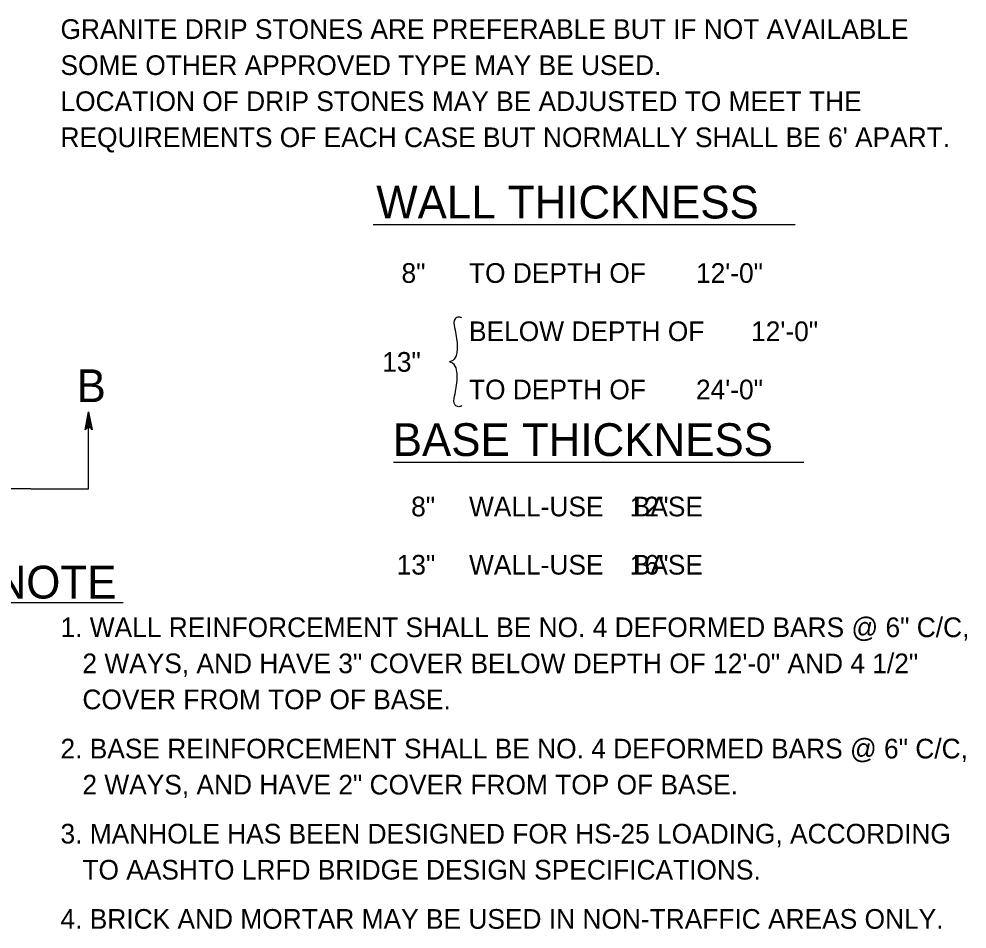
# Model space of a CAD drawing. Extents: x 0.2 to 7.1, y 1.2 to 11.2.
# Drawn here: x 3.289 to 6.18, y 8.474 to 11.25 of the extents above; entities that cross this region are included whole.
import ezdxf

# ---------------------------------------------------------------- set-up
doc = ezdxf.new("R2010")
doc.units = 0
for name, color, linetype in [('DETL-DIMS', 7, 'Continuous'), ('DETL-NOTE', 7, 'Continuous'), ('DETL-TITL', 7, 'Continuous')]:
    doc.layers.add(name, color=color, linetype=linetype)

msp = doc.modelspace()

# ---------------------------------------------------------------- linework, layer by layer
at = {"layer": 'DETL-DIMS'}
for p, q in [((3.5011, 9.8165), (3.5011, 10.0518)), ((3.3247, 9.8165), (2.4784, 9.8165)), ((3.3247, 9.8165), (3.5011, 9.8165))]:
    msp.add_line(p, q, dxfattribs=at)
msp.add_lwpolyline([(3.5011, 10.0518), (3.5114, 9.997), (3.5085, 10.0012), (3.5048, 10.0034), (3.5011, 10.004), (3.4975, 10.0034), (3.4938, 10.0012), (3.4909, 9.997), (3.5011, 10.0518), (3.4938, 10.0012), (3.4975, 10.0034), (3.5011, 10.0518), (3.5011, 10.004), (3.5048, 10.0034), (3.5011, 10.0518), (3.5085, 10.0012)], dxfattribs=at)
at = {"layer": 'DETL-NOTE'}
msp.add_line((3.2189, 9.4698), (3.6066, 9.4698), dxfattribs=at)
for points in [[(4.6393, 10.3383), (4.6303, 10.3406), (4.6187, 10.3357), (4.6171, 10.3087), (4.6219, 10.2817), (4.6251, 10.2533), (4.6115, 10.2087), (4.6017, 10.2038)], [(4.6393, 10.0697), (4.6303, 10.0674), (4.6187, 10.0723), (4.6171, 10.0993), (4.6219, 10.1263), (4.6251, 10.1547), (4.6115, 10.1993), (4.6017, 10.2042)]]:
    msp.add_spline(points, degree=3, dxfattribs=at)
at = {"layer": 'DETL-TITL'}
for p, q in [((4.3687, 10.6228), (5.6556, 10.6228)), ((4.431, 9.8983), (5.682, 9.8983))]:
    msp.add_line(p, q, dxfattribs=at)

# ---------------------------------------------------------------- texts
at = {"layer": 'DETL-NOTE'}
for s, height, p in [('GRANITE DRIP STONES ARE PREFERABLE BUT IF NOT AVAILABLE', 0.06, (3.4153, 11.189)), ('SOME OTHER APPROVED TYPE MAY BE USED.', 0.06, (3.4153, 11.079)), ('LOCATION OF DRIP STONES MAY BE ADJUSTED TO MEET THE', 0.06, (3.4153, 10.969)), ("REQUIREMENTS OF EACH CASE BUT NORMALLY SHALL BE 6' APART.", 0.06, (3.4153, 10.859)), ('8"', 0.06, (4.4552, 10.4451)), ('TO DEPTH OF ', 0.06, (4.661, 10.4451)), ('12\'-0"', 0.06, (5.3531, 10.4451)), ('BELOW DEPTH OF', 0.06, (4.661, 10.2674)), ('12\'-0"', 0.06, (5.5212, 10.2674)), ('13"', 0.06, (4.3963, 10.174)), ('B', 0.1, (3.4644, 10.0812)), ('TO DEPTH OF', 0.06, (4.661, 10.0898)), ('24\'-0"', 0.06, (5.3531, 10.0898)), ('8"', 0.06, (4.4846, 9.7329)), ('WALL-USE    BASE', 0.06, (4.661, 9.7329)), ('12"', 0.06, (5.1514, 9.7329)), ('13"', 0.06, (4.4404, 9.5553)), ('WALL-USE    BASE', 0.06, (4.661, 9.5553)), ('16"', 0.06, (5.1514, 9.5553)), ('NOTE', 0.1, (3.2143, 9.4823)), ('1. WALL REINFORCEMENT SHALL BE NO. 4 DEFORMED BARS @ 6" C/C,', 0.06, (3.4153, 9.3646)), ('   2 WAYS, AND HAVE 3" COVER BELOW DEPTH OF 12\'-0" AND 4 1/2"', 0.06, (3.4153, 9.2546)), ('   COVER FROM TOP OF BASE.', 0.06, (3.4153, 9.1446)), ('2. BASE REINFORCEMENT SHALL BE NO. 4 DEFORMED BARS @ 6" C/C,', 0.06, (3.4153, 8.9946)), ('   2 WAYS, AND HAVE 2" COVER FROM TOP OF BASE.', 0.06, (3.4153, 8.8846)), ('3. MANHOLE HAS BEEN DESIGNED FOR HS-25 LOADING, ACCORDING', 0.06, (3.4153, 8.7351)), ('   TO AASHTO LRFD BRIDGE DESIGN SPECIFICATIONS.', 0.06, (3.4153, 8.6251)), ('4. BRICK AND MORTAR MAY BE USED IN NON-TRAFFIC AREAS ONLY.', 0.06, (3.4153, 8.4751))]:
    msp.add_text(s, height=height, dxfattribs=at).set_placement(p)
at = {"layer": 'DETL-TITL'}
for s, p in [('WALL THICKNESS', (4.3781, 10.6414)), ('BASE THICKNESS', (4.4285, 9.9169))]:
    msp.add_text(s, height=0.1, dxfattribs=at).set_placement(p)

doc.saveas('drawing.dxf')
